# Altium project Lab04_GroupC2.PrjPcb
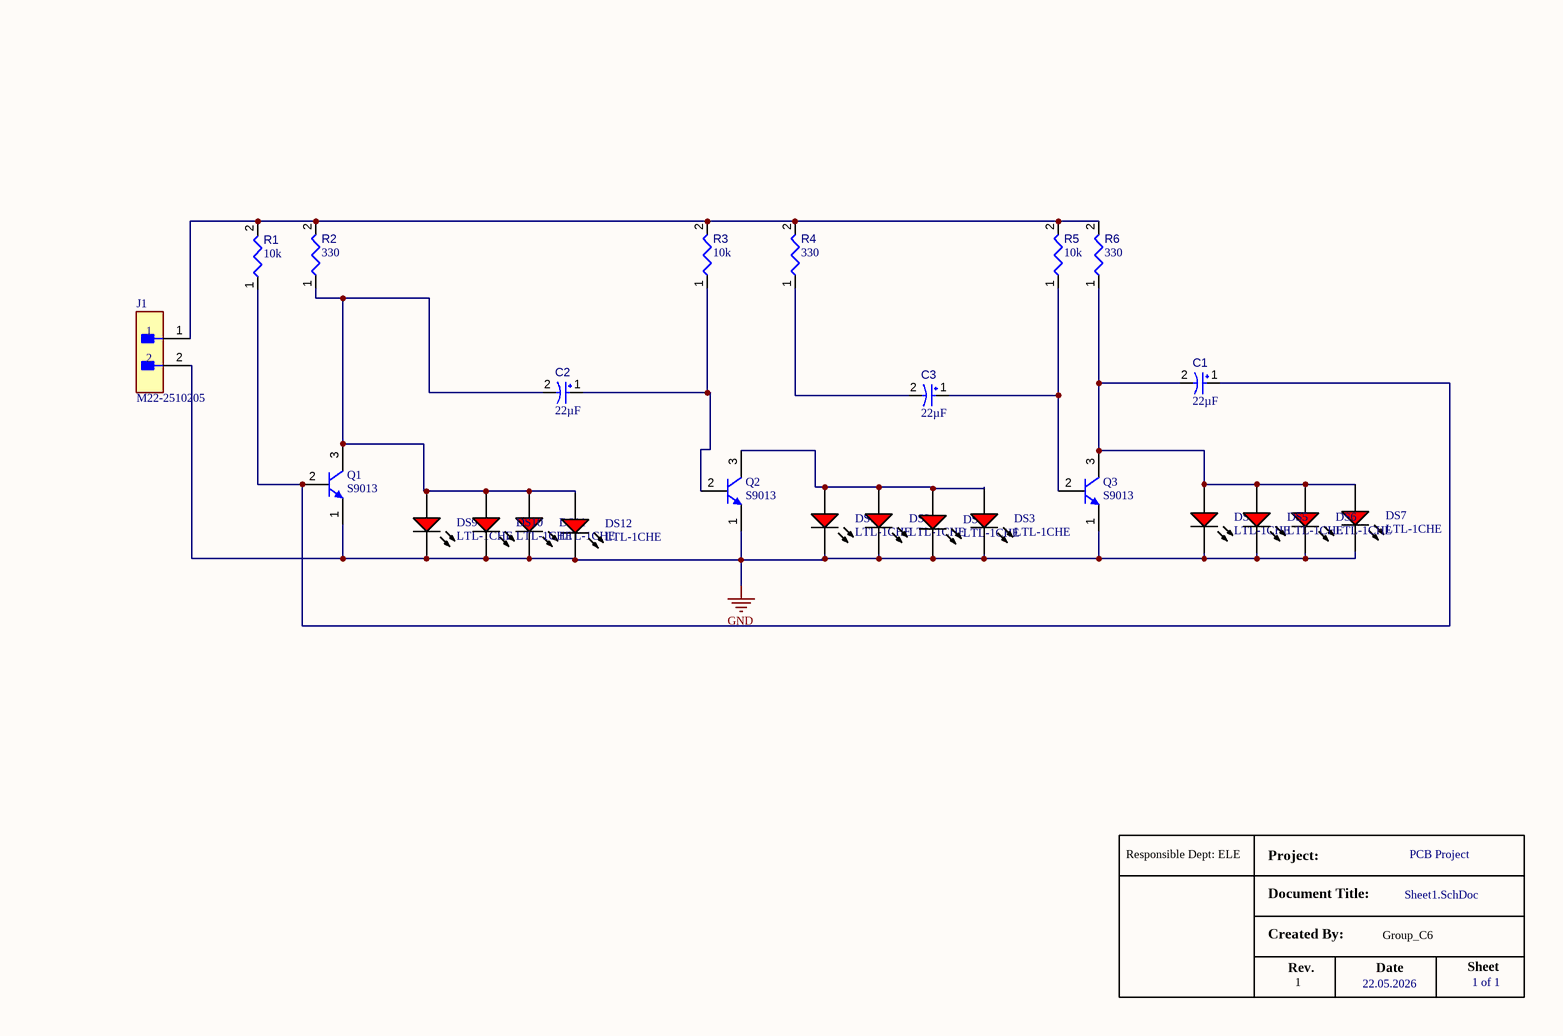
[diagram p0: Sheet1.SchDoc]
1 sheet, 26 parts. Net scope: global (net labels, ports and power ports of the same name join across sheets).
Board file: PCB1.PcbDoc

## Sheet Sheet1.SchDoc
size A4; SheetNumber: 1; SheetTotal: 1

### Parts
*  HSHL_Title_Block  (value not drawn)  (graphical)
C1  value 22µF  [KEMT-T491-D_M]  (hidden comment: T491D226K020AT)
C2  value 22µF  [KEMT-T491-D_M]  (hidden comment: T491D226K020AT)
C3  value 22µF  [KEMT-T491-D_M]  (hidden comment: T491D226K020AT)
DS1  LTL-1CHE  [INDPR60-254-520X380X650]
DS2  LTL-1CHE  [INDPR60-254-520X380X650]
DS3  LTL-1CHE  [INDPR60-254-520X380X650]
DS4  LTL-1CHE  [INDPR60-254-520X380X650]
DS5  LTL-1CHE  [INDPR60-254-520X380X650]
DS6  LTL-1CHE  [INDPR60-254-520X380X650]
DS7  LTL-1CHE  [INDPR60-254-520X380X650]
DS8  LTL-1CHE  [INDPR60-254-520X380X650]
DS9  LTL-1CHE  [INDPR60-254-520X380X650]
DS10  LTL-1CHE  [INDPR60-254-520X380X650]
DS11  LTL-1CHE  [INDPR60-254-520X380X650]
DS12  LTL-1CHE  [INDPR60-254-520X380X650]
J1  M22-2510205  [FP-M22-2510205-MFG]
Q1  S9013  [JSCJ-TO-92-3_V]
Q2  S9013  [JSCJ-TO-92-3_V]
Q3  S9013  [JSCJ-TO-92-3_V]
R1  value 10k  [RESA60-630X240]  (hidden comment: MFR-25FBF52-10K)
R2  value 330  [STA_CF18_STP]  (hidden comment: CF18JT330R)
R3  value 10k  [RESA60-630X240]  (hidden comment: MFR-25FBF52-10K)
R4  value 330  [STA_CF18_STP]  (hidden comment: CF18JT330R)
R5  value 10k  [RESA60-630X240]  (hidden comment: MFR-25FBF52-10K)
R6  value 330  [STA_CF18_STP]  (hidden comment: CF18JT330R)

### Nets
GND: DS1.2(K) DS2.2(K) DS3.2(K) DS4.2(K) DS5.2(K) DS6.2(K) DS7.2(K) DS8.2(K) DS9.2(K) DS10.2(K) DS11.2(K) DS12.2(K) J1.2 Q1.1(E) Q2.1(E) Q3.1(E)
NetC1_1: C1.1 Q1.2(B) R1.1
NetC1_2: C1.2 DS4.1(A) DS5.1(A) DS6.1(A) DS7.1(A) Q3.3(C) R6.1
NetC2_1: C2.1 Q2.2(B) R3.1
NetC2_2: C2.2 DS9.1(A) DS10.1(A) DS11.1(A) DS12.1(A) Q1.3(C) R2.1
NetC3_1: C3.1 Q3.2(B) R5.1
NetC3_2: C3.2 R4.1
NetDS1_1: DS1.1(A) DS2.1(A) DS3.1(A) DS8.1(A) Q2.3(C)
NetJ1_1: J1.1 R1.2 R2.2 R3.2 R4.2 R5.2 R6.2

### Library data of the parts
* = Title_Block_Riwaj
C1-C3 = CMP-001-00038-7: Tantalum Surface Mount Capacitor-Standard Tantalum, 22 uF, +/- 10%, 20 V, -55 to 125 degC, 2917 (7343 Metric), RoHS, Tape and Reel; Manufacturer: Kemet; ESR: 800mohm; Voltage Rating: 20V; Ripple Current: 433mA; Resistance: 0.8Ohm
DS1-DS12 = CMP-007-00018-2: LED Uni-Color Red, 100 mW, 30 mA, -55 to 100 degC, 2-Pin THD, RoHS, Bulk; Manufacturer: Lite-On; Forward Current: 20mA; Nominal Vf: 2V; Viewing Angle: 60degrees; Luminous Intensity: 12.6mcd; Lens Style: Dome
J1 = CMP-002-00072-1: Conn Unshrouded Header M 2 POS 2mm Solder ST Top Entry Thru-Hole Bulk/Loose; Max Current Rating: 1A; Gender: Male; Voltage Rating: 650V; Connector Type: Male Pin
Q1-Q3 = CMP-013-00000-3: Transistor, NPN, 0.1 uA, 150 MHz, 3-Pin TO-92; Manufacturer: Jiangsu Changjiang Electronics Technology
R1 R3 R5 = CMP-009-00047-4: Axial Resistor, 10 KOhm, +/- 1%, 0.25 W, -55 to 155 degC, 2-Pin THD, RoHS, Bulk; Manufacturer: Yageo; Power: 250mW; Voltage Rating: 250V
R2 R4 R6 = CMP-009-00177-2: Fixed Resistor, Carbon Film, 0.125W, 330ohm, 250V, 5% +/-Tol, -400, 0ppm/Cel, Through Hole Mount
